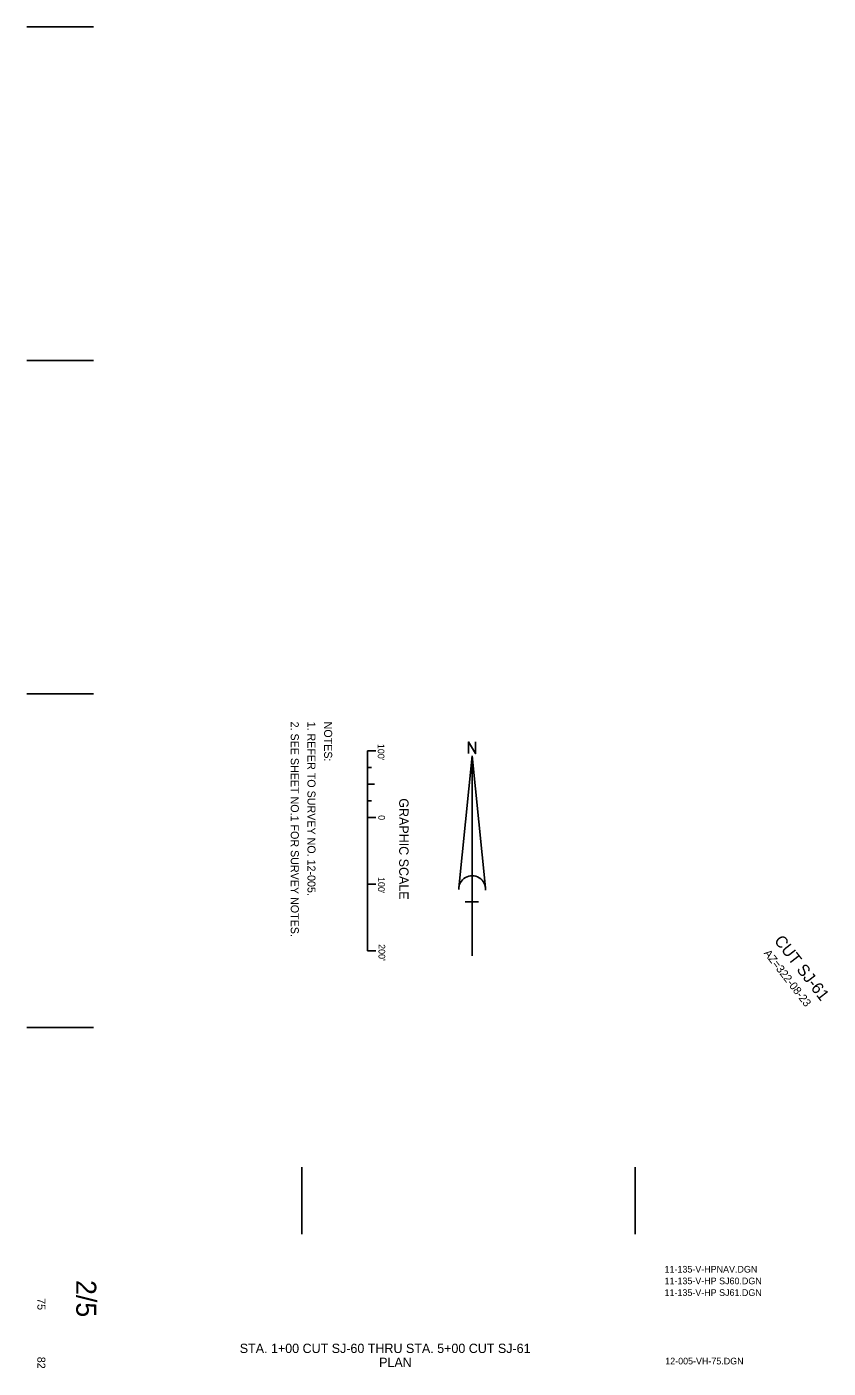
# Model space of a CAD drawing. Extents: x 576588 to 579788, y 1955489 to 1959590.
# Drawn here: x 576588 to 577789, y 1955489 to 1957500 of the extents above; entities that cross this region are included whole.
import ezdxf

# ---------------------------------------------------------------- set-up
doc = ezdxf.new("R2010")
doc.units = 0
for name, color, linetype in [('V-ANNO-DIMS', 7, 'Continuous'), ('V-ANNO-PATT', 7, 'Continuous'), ('V-ANNO-RDME', 7, 'Continuous'), ('V-ANNO-SYMB', 7, 'Continuous'), ('V-DUCT-MULT', 7, 'Continuous')]:
    doc.layers.add(name, color=color, linetype=linetype)

msp = doc.modelspace()

# ---------------------------------------------------------------- linework, layer by layer
at = {"layer": 'V-ANNO-PATT'}
for p, q in [((577098.6, 1956414.6), (577098.6, 1956114.6)), ((577098.6, 1956414.6), (577111.1, 1956414.6)), ((577235.4, 1956209.3), (577255.3, 1956407.3)), ((577255.3, 1956107.3), (577255.3, 1956407.3)), ((577275.2, 1956209.3), (577255.3, 1956407.3)), ((577098.9, 1956389.6), (577104.6, 1956389.6)), ((577098.6, 1956364.6), (577108.8, 1956364.6)), ((577098.9, 1956364.6), (577104.6, 1956364.6)), ((577098.9, 1956339.6), (577104.6, 1956339.6)), ((577098.6, 1956314.6), (577111.1, 1956314.6)), ((577098.6, 1956314.6), (577104.6, 1956314.6)), ((577098.6, 1956314.6), (577111.1, 1956314.6)), ((577098.6, 1956214.6), (577111.1, 1956214.6)), ((577264.8, 1956188.3), (577244.8, 1956188.3)), ((577098.6, 1956114.6), (577111.1, 1956114.6))]:
    msp.add_line(p, q, dxfattribs=at)
msp.add_lwpolyline([(577249.8, 1956410.5), (577249.8, 1956428), (577260.6, 1956410.5), (577260.6, 1956428)], dxfattribs=at)
msp.add_arc((577255.3, 1956207.3), 20, 355.2984, 182.0673, dxfattribs=at)
at = {"layer": 'V-DUCT-MULT'}
for p, q in [((576587.8, 1957500), (576687.8, 1957500)), ((576587.8, 1957000), (576687.8, 1957000)), ((576587.8, 1956500), (576687.8, 1956500)), ((576587.8, 1956000), (576687.8, 1956000)), ((577000, 1955790.2), (577000, 1955690.2)), ((577500, 1955790.2), (577500, 1955690.2))]:
    msp.add_line(p, q, dxfattribs=at)

# ---------------------------------------------------------------- texts
at = {"layer": 'V-ANNO-DIMS'}
for s, height, rotation, p in [('11-135-V-HPNAV.DGN                  ', 10, 360, (577543.9, 1955632.4)), ('11-135-V-HP SJ60.DGN                ', 10, 360, (577543.9, 1955614.9)), (' 2/5  ', 30, 270, (576661.9, 1955632.4)), ('11-135-V-HP SJ61.DGN                ', 10, 360, (577543.9, 1955597.4)), (' 75 ', 12, 270, (576603.6, 1955598.5)), ('      STA. 1+00 CUT SJ-60 THRU STA. 5+00 CUT SJ-61     ', 14, 360, (576875.8, 1955511.8)), (' 82 ', 12, 270, (576603.6, 1955510.6)), ('                          PLAN                         ', 14, 360, (576980.7, 1955490.8)), ('12-005-VH-75.DGN                    ', 10, 360, (577544.9, 1955494.7))]:
    msp.add_text(s, height=height, rotation=rotation, dxfattribs=at).set_placement(p)
at = {"layer": 'V-ANNO-PATT'}
for s, height, p in [("100'", 10, (577113.9, 1956425)), ('GRAPHIC SCALE', 14, (577146, 1956343.4)), ('0', 10, (577114.7, 1956318.2)), ("100'", 10, (577114.3, 1956225.4)), ("200'", 10, (577115, 1956124.8))]:
    msp.add_text(s, height=height, rotation=270, dxfattribs=at).set_placement(p)
at = {"layer": 'V-ANNO-RDME'}
for s, p in [('2. SEE SHEET NO.1 FOR SURVEY NOTES.', (576983.5, 1956458.4)), ('1. REFER TO SURVEY NO. 12-005.', (577008.5, 1956458.4)), ('NOTES:', (577033.5, 1956458.4))]:
    msp.add_text(s, height=12, rotation=270, dxfattribs=at).set_placement(p)
at = {"layer": 'V-ANNO-SYMB'}
for s, height, p in [('CUT SJ-61', 17.52, (577707.3, 1956129.7)), ('AZ=322-08-23', 12, (577692, 1956111))]:
    msp.add_text(s, height=height, rotation=307.8605, dxfattribs=at).set_placement(p)

doc.saveas('drawing.dxf')
